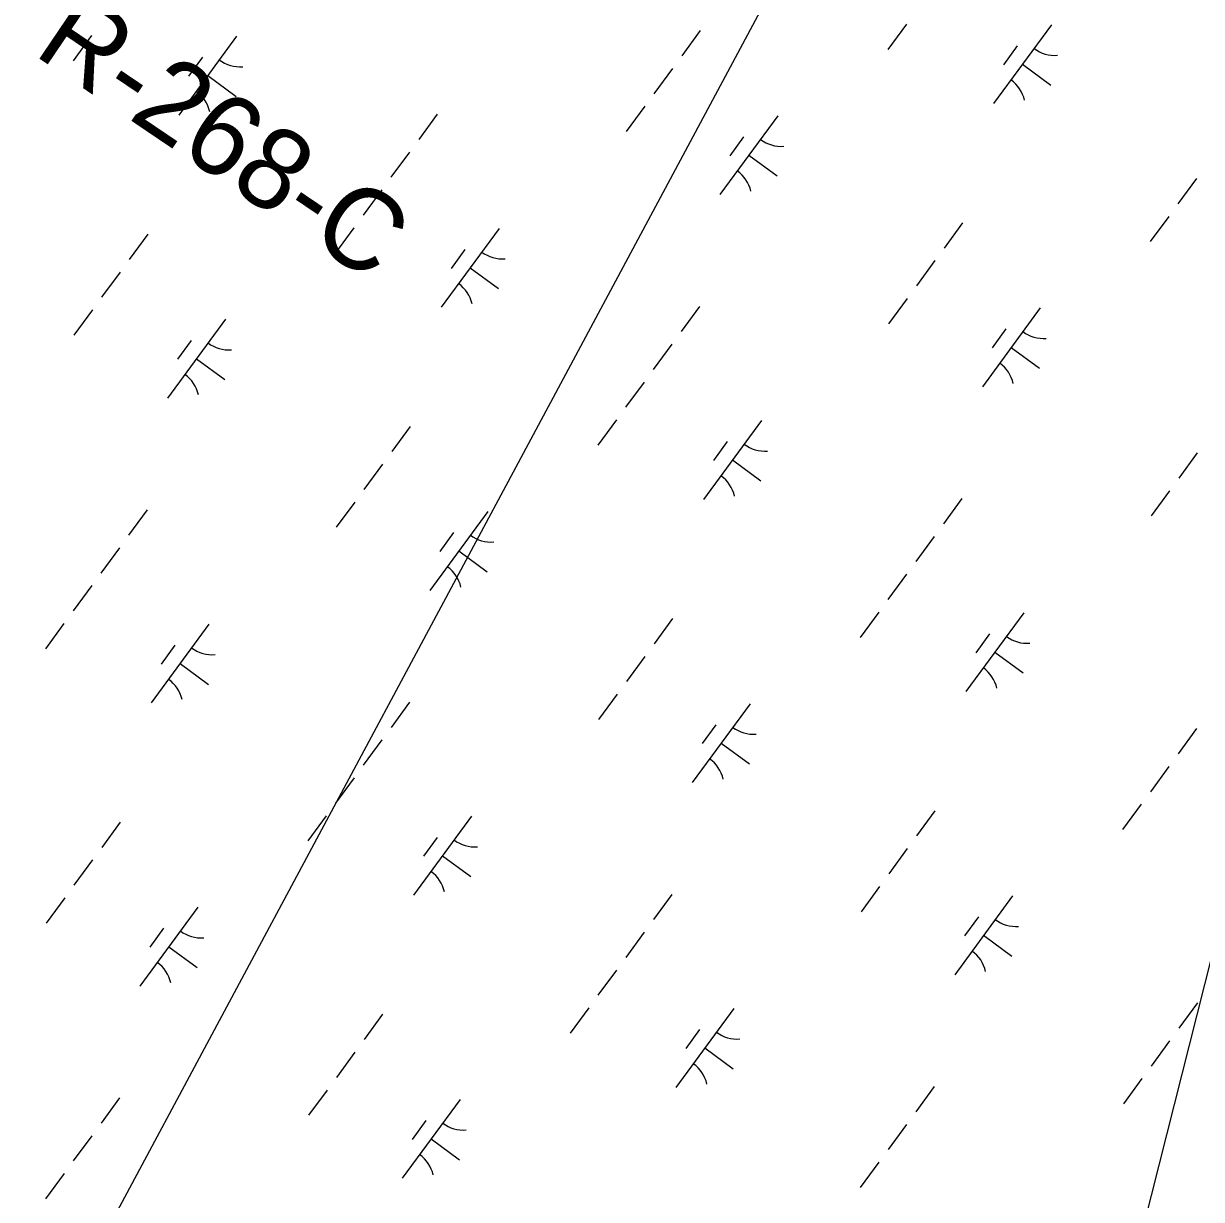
# Model space of a CAD drawing. Extents: x 3905714 to 3926767, y 183354 to 205755.
# Drawn here: x 3918084 to 3918686, y 191979 to 192580 of the extents above; entities that cross this region are included whole.
import ezdxf

# ---------------------------------------------------------------- set-up
doc = ezdxf.new("R2010")
doc.units = 0
for name, color, linetype in [('V-RIVR-RANG-IDEN', 7, 'Continuous'), ('V-UTIL-LINE', 7, 'Continuous'), ('V-WETL-SWMP', 7, 'Continuous')]:
    doc.layers.add(name, color=color, linetype=linetype)

msp = doc.modelspace()

# ---------------------------------------------------------------- linework, layer by layer
at = {"layer": 'V-UTIL-LINE'}
for points in [[(3922094.67, 198742.56), (3921080.02, 197477.61), (3915734.79, 187496.67)], [(3915141.88, 186857.82), (3915602.26, 187412.44), (3917208.62, 188427.22), (3918201.85, 190592.37), (3918499.52, 191341.67), (3918705.19, 192156.56), (3920335.23, 195367.27), (3921815.24, 198099.69), (3922187.19, 198661.56)]]:
    msp.add_lwpolyline(points, dxfattribs=at)
at = {"layer": 'V-WETL-SWMP'}
for p, q in [((3918430.13, 192576.8), (3918420.68, 192563.89)), ((3918535.55, 192580.09), (3918526.09, 192567.19)), ((3918609.73, 192579.76), (3918580.18, 192539.43)), ((3918118.87, 192574.27), (3918109.42, 192561.36)), ((3918193.06, 192573.94), (3918163.51, 192533.61)), ((3918175.6, 192563.17), (3918168.51, 192553.49)), ((3918592.28, 192569), (3918585.18, 192559.32)), ((3918415.95, 192557.44), (3918406.49, 192544.53)), ((3918594.95, 192559.6), (3918609.47, 192548.96)), ((3918178.28, 192553.77), (3918192.8, 192543.13)), ((3918295.6, 192534.04), (3918286.15, 192521.13)), ((3918401.77, 192538.08), (3918392.31, 192525.17)), ((3918469.78, 192533.25), (3918440.23, 192492.92)), ((3918452.32, 192522.48), (3918445.23, 192512.8)), ((3918281.42, 192514.68), (3918271.96, 192501.77)), ((3918455, 192513.08), (3918469.52, 192502.44)), ((3918683.91, 192501.15), (3918674.45, 192488.24)), ((3918267.24, 192495.32), (3918257.78, 192482.41)), ((3918669.73, 192481.79), (3918660.27, 192468.88)), ((3918253.05, 192475.96), (3918243.6, 192463.05)), ((3918327.24, 192475.63), (3918297.69, 192435.3)), ((3918564.31, 192478.49), (3918554.86, 192465.59)), ((3918147.64, 192472.67), (3918138.18, 192459.76)), ((3918309.78, 192464.87), (3918302.69, 192455.19)), ((3918312.46, 192455.47), (3918326.98, 192444.83)), ((3918550.13, 192459.13), (3918540.67, 192446.23)), ((3918133.46, 192453.31), (3918124, 192440.4)), ((3918535.95, 192439.77), (3918526.49, 192426.87)), ((3918119.27, 192433.95), (3918109.82, 192421.04)), ((3918429.78, 192435.74), (3918420.33, 192422.83)), ((3918603.95, 192434.94), (3918574.4, 192394.61)), ((3918187.28, 192429.12), (3918157.73, 192388.78)), ((3918586.5, 192424.18), (3918579.41, 192414.5)), ((3918169.83, 192418.35), (3918162.74, 192408.67)), ((3918415.6, 192416.38), (3918406.14, 192403.47)), ((3918589.18, 192414.78), (3918603.7, 192404.14)), ((3918172.51, 192408.95), (3918187.03, 192398.31)), ((3918401.42, 192397.02), (3918391.96, 192384.11)), ((3918387.23, 192377.66), (3918377.78, 192364.75)), ((3918461.42, 192377.33), (3918431.87, 192336.99)), ((3918281.82, 192374.36), (3918272.36, 192361.46)), ((3918443.96, 192366.56), (3918436.87, 192356.88)), ((3918684.31, 192360.83), (3918674.85, 192347.92)), ((3918267.64, 192355), (3918258.18, 192342.1)), ((3918446.64, 192357.16), (3918461.16, 192346.52)), ((3918670.13, 192341.47), (3918660.67, 192328.56)), ((3918253.45, 192335.64), (3918244, 192322.74)), ((3918563.96, 192337.43), (3918554.51, 192324.52)), ((3918147.29, 192331.6), (3918137.83, 192318.7)), ((3918321.46, 192330.81), (3918291.91, 192290.48)), ((3918304.01, 192320.04), (3918296.92, 192310.36)), ((3918549.78, 192318.07), (3918540.32, 192305.16)), ((3918133.11, 192312.24), (3918123.65, 192299.34)), ((3918306.69, 192310.65), (3918321.21, 192300.01)), ((3918535.6, 192298.71), (3918526.14, 192285.8)), ((3918118.92, 192292.88), (3918109.47, 192279.98)), ((3918416, 192276.06), (3918406.54, 192263.15)), ((3918521.41, 192279.35), (3918511.96, 192266.44)), ((3918595.59, 192279.02), (3918566.04, 192238.69)), ((3918104.74, 192273.52), (3918095.28, 192260.62)), ((3918178.92, 192273.2), (3918149.37, 192232.86)), ((3918578.14, 192268.25), (3918571.05, 192258.57)), ((3918161.47, 192262.43), (3918154.38, 192252.75)), ((3918401.82, 192256.7), (3918392.36, 192243.79)), ((3918580.82, 192258.85), (3918595.34, 192248.22)), ((3918164.15, 192253.03), (3918178.67, 192242.39)), ((3918281.47, 192233.3), (3918272.01, 192220.39)), ((3918387.63, 192237.34), (3918378.18, 192224.43)), ((3918455.64, 192232.51), (3918426.09, 192192.17)), ((3918438.19, 192221.74), (3918431.1, 192212.06)), ((3918683.96, 192219.76), (3918674.5, 192206.86)), ((3918267.29, 192213.94), (3918257.83, 192201.03)), ((3918440.87, 192212.34), (3918455.39, 192201.7)), ((3918669.77, 192200.4), (3918660.32, 192187.5)), ((3918253.1, 192194.58), (3918243.65, 192181.67)), ((3918550.18, 192177.75), (3918540.72, 192164.84)), ((3918655.59, 192181.04), (3918646.13, 192168.14)), ((3918133.51, 192171.93), (3918124.05, 192159.02)), ((3918238.92, 192175.22), (3918229.46, 192162.31)), ((3918313.1, 192174.89), (3918283.55, 192134.56)), ((3918295.65, 192164.12), (3918288.56, 192154.44)), ((3918298.33, 192154.72), (3918312.85, 192144.09)), ((3918535.99, 192158.39), (3918526.54, 192145.48)), ((3918119.32, 192152.57), (3918109.87, 192139.66)), ((3918521.81, 192139.03), (3918512.35, 192126.12)), ((3918105.14, 192133.21), (3918095.68, 192120.3)), ((3918415.65, 192134.99), (3918406.19, 192122.09)), ((3918589.82, 192134.2), (3918560.27, 192093.87)), ((3918173.15, 192128.37), (3918143.6, 192088.04)), ((3918572.37, 192123.43), (3918565.27, 192113.75)), ((3918155.69, 192117.61), (3918148.6, 192107.93)), ((3918401.46, 192115.63), (3918392.01, 192102.73)), ((3918575.04, 192114.03), (3918589.56, 192103.4)), ((3918158.37, 192108.21), (3918172.89, 192097.57)), ((3918387.28, 192096.27), (3918377.82, 192083.37)), ((3918373.1, 192076.91), (3918363.64, 192064.01)), ((3918447.28, 192076.58), (3918417.73, 192036.25)), ((3918684.36, 192079.45), (3918674.9, 192066.54)), ((3918267.68, 192073.62), (3918258.23, 192060.71)), ((3918429.83, 192065.82), (3918422.74, 192056.14)), ((3918670.17, 192060.09), (3918660.72, 192047.18)), ((3918253.5, 192054.26), (3918244.04, 192041.35)), ((3918432.51, 192056.42), (3918447.03, 192045.78)), ((3918655.99, 192040.73), (3918646.53, 192027.82)), ((3918239.32, 192034.9), (3918229.86, 192021.99)), ((3918549.83, 192036.69), (3918540.37, 192023.78)), ((3918133.15, 192030.86), (3918123.7, 192017.95)), ((3918307.33, 192030.07), (3918277.78, 191989.74)), ((3918289.87, 192019.3), (3918282.78, 192009.62)), ((3918535.64, 192017.33), (3918526.19, 192004.42)), ((3918118.97, 192011.5), (3918109.51, 191998.59)), ((3918292.55, 192009.9), (3918307.07, 191999.26)), ((3918521.46, 191997.97), (3918512, 191985.06)), ((3918104.79, 191992.14), (3918095.33, 191979.23))]:
    msp.add_line(p, q, dxfattribs=at)
for centre, start, end in [((3918611.47, 192581.74), 232.99998, 274.54364), ((3918194.8, 192575.91), 232.99998, 274.54364), ((3918578.82, 192537.18), 12.99998, 54.54364), ((3918162.15, 192531.35), 12.99998, 54.54364), ((3918471.52, 192535.22), 232.99998, 274.54364), ((3918438.87, 192490.66), 12.99998, 54.54364), ((3918328.98, 192477.61), 232.99998, 274.54364), ((3918296.33, 192433.04), 12.99998, 54.54364), ((3918605.7, 192436.92), 232.99998, 274.54364), ((3918189.02, 192431.09), 232.99998, 274.54364), ((3918573.05, 192392.35), 12.99998, 54.54364), ((3918156.37, 192386.53), 12.99998, 54.54364), ((3918463.16, 192379.3), 232.99998, 274.54364), ((3918430.51, 192334.74), 12.99998, 54.54364), ((3918323.2, 192332.79), 232.99998, 274.54364), ((3918290.55, 192288.22), 12.99998, 54.54364), ((3918597.34, 192281), 232.99998, 274.54364), ((3918180.66, 192275.17), 232.99998, 274.54364), ((3918564.69, 192236.43), 12.99998, 54.54364), ((3918148.01, 192230.61), 12.99998, 54.54364), ((3918457.38, 192234.48), 232.99998, 274.54364), ((3918424.73, 192189.92), 12.99998, 54.54364), ((3918314.84, 192176.86), 232.99998, 274.54364), ((3918282.19, 192132.3), 12.99998, 54.54364), ((3918591.56, 192136.17), 232.99998, 274.54364), ((3918174.89, 192130.35), 232.99998, 274.54364), ((3918558.91, 192091.61), 12.99998, 54.54364), ((3918142.24, 192085.79), 12.99998, 54.54364), ((3918449.02, 192078.56), 232.99998, 274.54364), ((3918416.37, 192034), 12.99998, 54.54364), ((3918309.07, 192032.04), 232.99998, 274.54364), ((3918276.42, 191987.48), 12.99998, 54.54364)]:
    msp.add_arc(centre, 17.62, start, end, dxfattribs=at)

# ---------------------------------------------------------------- texts
at = {"layer": 'V-RIVR-RANG-IDEN'}
msp.add_text('R-268-C', height=41.5, rotation=325.93555, dxfattribs=at).set_placement((3918088.42, 192565))

doc.saveas('drawing.dxf')
